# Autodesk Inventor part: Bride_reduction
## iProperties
Shininess: 64.0
Length Units: 11269
Angle Units: 11279
Time Units: 11290
Mass Units: 11283
Length Display Precision: 3
Angle Display Precision: 2
Compacted: True
Part Number: Bride_reduction
Document SubType Name: Modeling
Created: 2008-02
Material: Par défaut
Designer: Pascal
Density: 0.0
Volumn: 0.0
Area: 0.0
PropertySet Name: Model Information
Control State: 0
Master: False
Checked Out: False
MATIERE_PIECE: X2CrNi 18-11
OBSERVATIONS: ep. 8
DESIGNATION: Bride DN 150
Author: Pascal
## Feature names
1. Extrusion1
2. Extrusion2
3. Réseau circulaire1 [Circular Pattern]
